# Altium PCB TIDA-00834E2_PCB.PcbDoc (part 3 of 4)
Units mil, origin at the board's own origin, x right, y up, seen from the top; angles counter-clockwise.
Board outline 7480.31 x 4133.86 mil, 4 copper layers (Top Layer, GND, PWR, Bottom Layer), stack 61.912 mil thick; 550 components, 248 nets, 1167 pads, 312 vias.
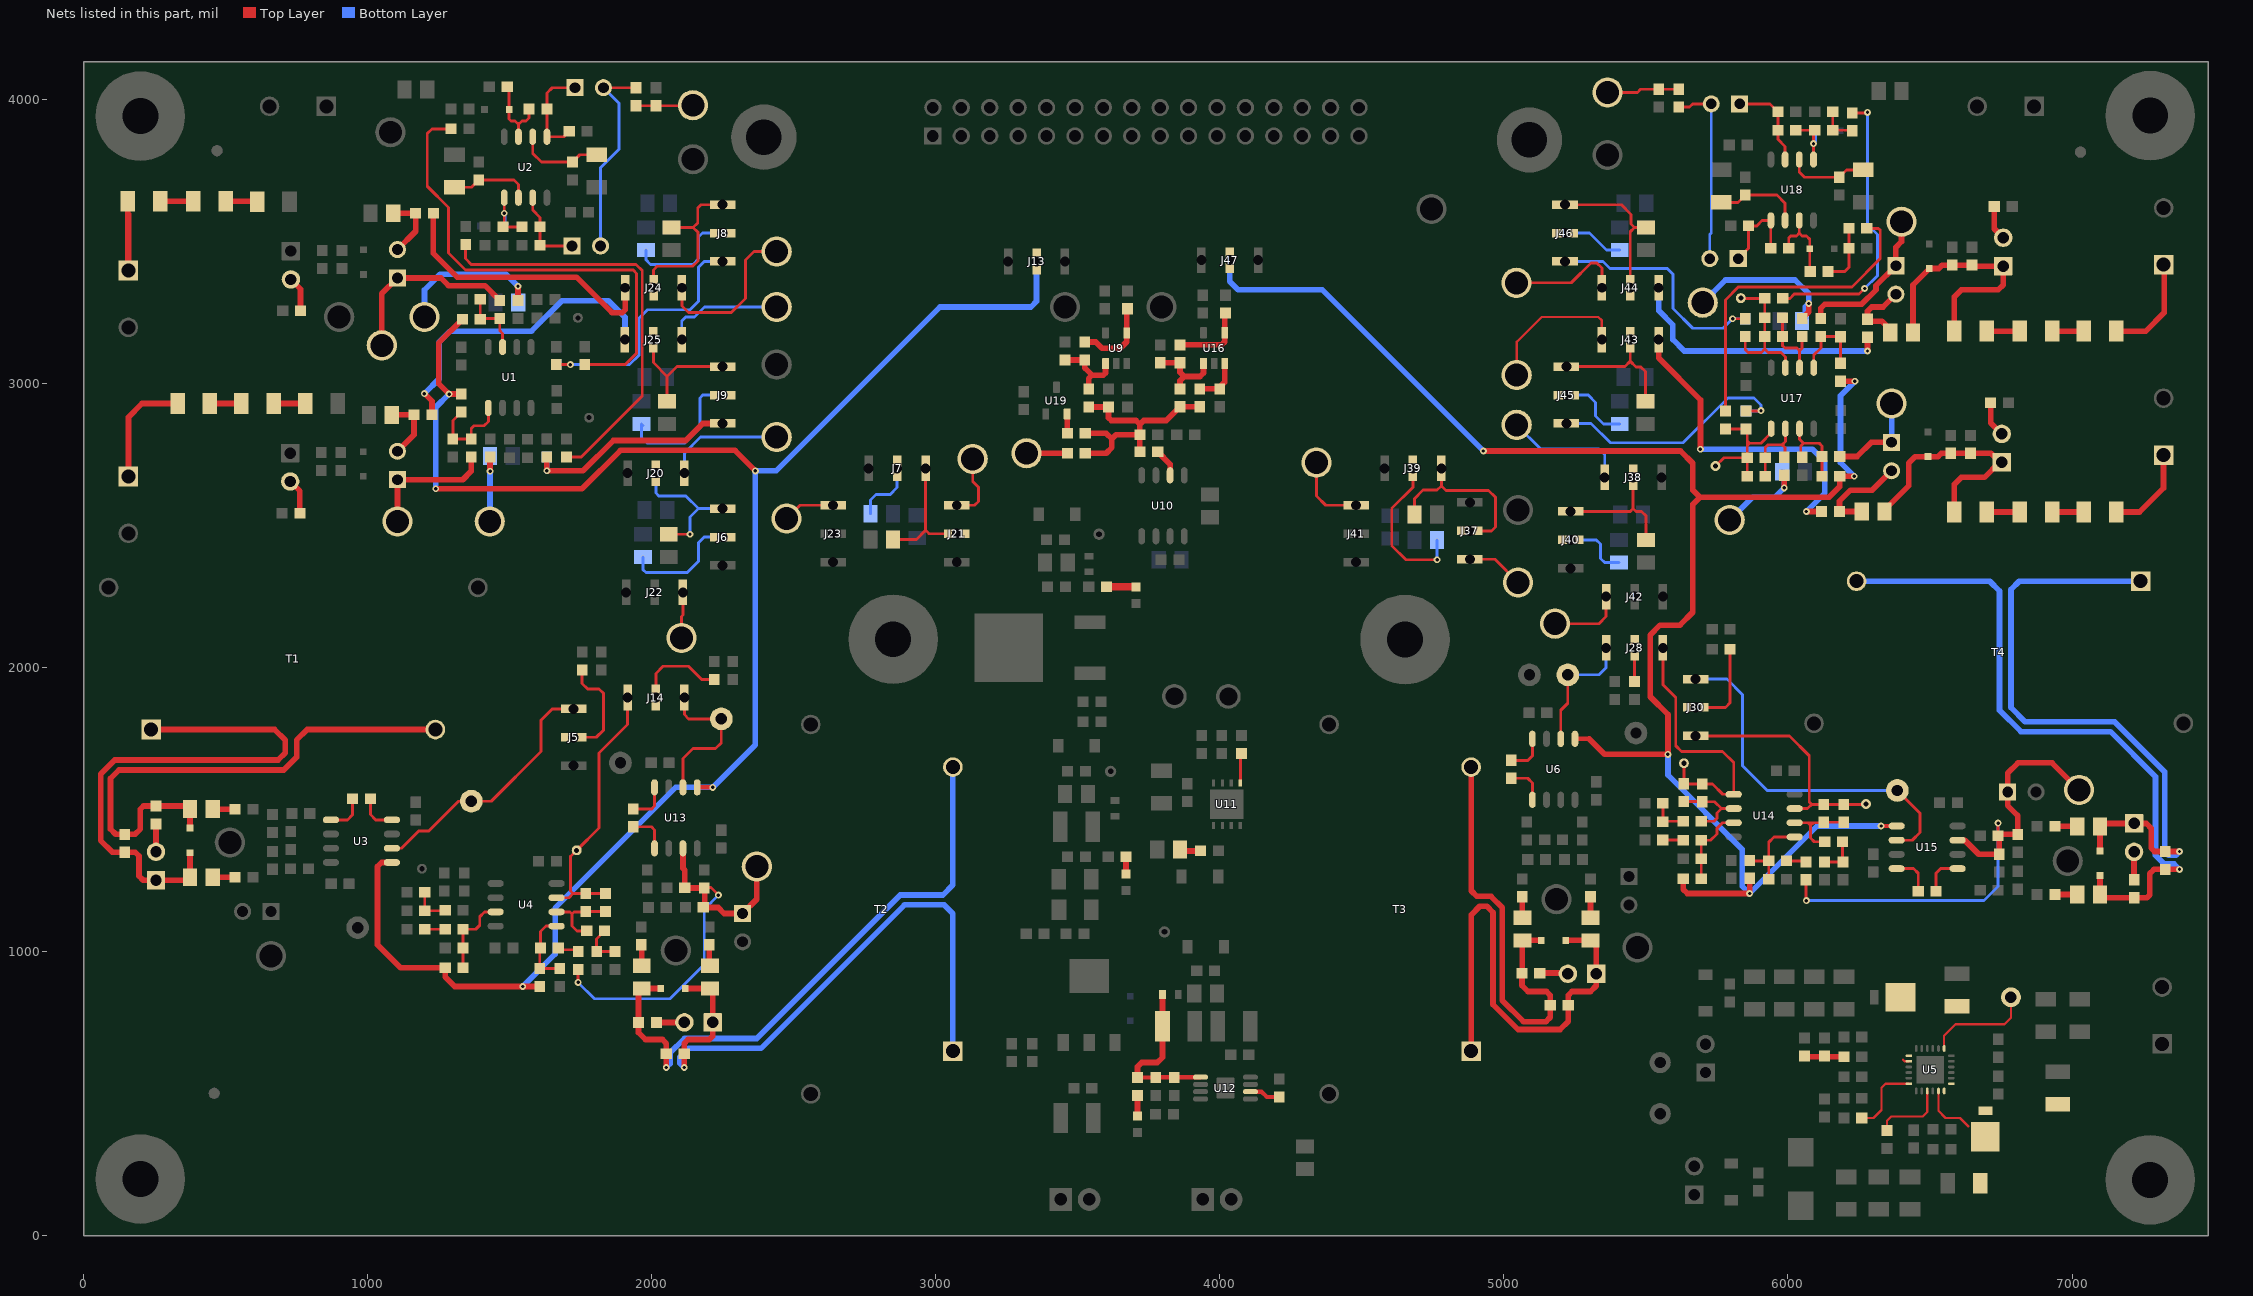
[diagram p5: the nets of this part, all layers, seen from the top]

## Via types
v1: diameter 24, hole 12, Top Layer to Bottom Layer, tented both sides, 295 vias
v2: diameter 19.68, hole 7.87, Top Layer to Bottom Layer, tented both sides, 15 vias
v3: diameter 40, hole 20, Top Layer to Bottom Layer, 2 vias

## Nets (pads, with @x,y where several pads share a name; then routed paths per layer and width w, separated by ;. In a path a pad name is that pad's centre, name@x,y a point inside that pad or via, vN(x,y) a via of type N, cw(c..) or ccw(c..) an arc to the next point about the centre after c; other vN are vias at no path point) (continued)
NetC70_2: C70.2 C72.2 FB3.1 R84.2 R85.2 U12.1 | length 584.2
  Top Layer w15: R84.2@3710.31,557.25 R85.2@3774.04,557.25 3775.44,558.65 U12.1@3932.4,558.65
  Top Layer w20: R84.2@3710.31,557.25 3710.31,595.31 3725,610 3780,610 3798.22,628.22 C72.2@3798.22,737.75 FB3.1@3798.22,850.13
NetC73_1: C73.1 R83.1 | length 74.3
  Top Layer w20: C73.1@3860,1360 3865,1355 R83.1@3932.2,1355
NetC74_2: C74.2 U12.6 | length 109.2
  Top Layer w15: U12.6@4107.6,507.47 4146.84,507.47 4165.54,488.77 C74.2@4209.04,488.77
NetC77_1: C77.1 C78.1 J26.1 R90.2 R104.2 TP25.1 U13.3 | length 1497.1
  Top Layer w10: v1(1741.08,892.32) R104.2@1741.08,937.73 ; R90.2@2185,1224.4 2186.5,1225.9 2208.5,1225.9 v1(2235,1199.4)
  Top Layer w20: U13.3@2110,1364.17 2110,1293.83 2116.5,1287.34 C78.1@2116.5,1225.9 2117.99,1224.4 R90.2@2185,1224.4 2186.5,1222.91 2186.5,1155.9 2234.1,1155.9 2255,1135 J26.1@2320,1135 2370,1185 TP25.1@2370,1300
  Bottom Layer w10: v1(1741.08,892.32) 1798.99,834.4 2064.4,834.4 2185,955 2185,1149.4 v1(2235,1199.4)
NetC82_1: C82.1 R97.2 R98.1 U4.6 | length 280.2
  Top Layer w10: U4.6@1665.24,1140.34 1712.81,1140.34 1719.76,1133.4 ; R98.1@1771.12,1073.4 1736.76,1073.4 1719.76,1090.4 1719.76,1133.4 ; R97.2@1837.61,1141.9 C82.1@1767.61,1141.9 1766.11,1140.4 1726.76,1140.4 1719.76,1133.4
NetC82_2: C82.2 J14.3 R97.1 TP30.1 U4.7 | length 955
  Top Layer w10: U4.7@1665.24,1190.34 1708.7,1190.34 1723.25,1204.89 ; R97.1@1837.61,1204.89 C82.2@1767.61,1204.89 1723.25,1204.89 ; J14.3@1915,1895 1915,1800 1815,1700 1815,1436.24 TP30.1@1736.08,1357.32 1714.76,1336 1714.76,1213.39 1723.25,1204.89
NetC88_1: C88.1 R115.2 R117.1 U14.2 | length 285.9
  Top Layer w10: R115.2@5633.7,1528.5 5697.64,1528.5 C88.1@5698.17,1527.97 5742.03,1527.97 5765.71,1504.29 ; R117.1@5694.66,1459.46 5739.46,1459.46 5750,1470 5750,1488.58 5765.71,1504.29 ; U14.2@5809.09,1504.29 5765.71,1504.29
NetC88_2: C88.2 J28.3 R115.1 TP28.1 U14.1 | length 966.8
  Top Layer w10: J28.3@5560,2070 5560,1940 5605,1895 5605,1725 5625,1705 5770,1705 5809.09,1665.91 U14.1@5809.09,1554.29 5770.71,1554.29 5734.04,1590.96 C88.2@5698.17,1590.96 5634.23,1590.96 R115.1@5633.7,1591.5 TP28.1@5633.7,1663.7
NetC94_1: C94.1 C95.1 J29.1 R123.2 R129.2 TP38.1 U15.3 | length 1876.6
  Top Layer w10: R129.2@6063.7,1253.5 6063.7,1181.3 v1(6065,1180) ; R123.2@6740,1407.8 v1(6740,1452.8)
  Top Layer w20: U15.3@6597.28,1392.8 6622.33,1392.8 6671.81,1343.31 C95.1@6743.51,1343.31 6743.51,1404.29 R123.2@6740,1407.8 6745.52,1413.31 C94.1@6808.5,1413.31 6808.5,1480 6773.5,1515 J29.1@6773.5,1562.8 6773.5,1628.5 6810,1665 6930,1665 TP38.1@7025,1570
  Bottom Layer w10: v1(6065,1180) 6690,1180 6740,1230 v1(6740,1452.8)
NetC99_1: C99.1 R131.2 R133.1 U14.6 | length 299.1
  Top Layer w10: U14.6@6023.65,1454.29 6089.29,1454.29 ; 6070.71,1454.29 6080,1445 ; R133.1@6129.53,1387.34 6092.66,1387.34 6080,1400 6080,1445 ; R131.2@6196.02,1455.84 C99.1@6126.02,1455.84 6124.47,1454.29 6089.29,1454.29 ; 6080,1445 6089.29,1454.29
NetC99_2: C99.2 J30.3 R131.1 TP41.1 U14.7 | length 861.7
  Top Layer w10: J30.3@5675,1760 6005,1760 6075,1690 6075,1527.67 6083.83,1518.83 ; U14.7@6023.65,1504.29 6069.29,1504.29 6083.83,1518.83 ; TP41.1@6275,1520 6273.83,1518.83 R131.1@6196.02,1518.83 C99.2@6126.02,1518.83 6083.83,1518.83
NetC101_1: C101.1 R138.2 R143.1 U17.2 | length 275.5
  Top Layer w10: R138.2@5919.86,2674.33 C101.1@5919.86,2739.33 5919.86,2774.86 5930,2785 5980,2785 ; R143.1@5986.71,2740.82 5990,2744.11 5990,2775 5980,2785 ; U17.2@5990.96,2841.42 5990.96,2795.96 5980,2785
NetC101_2: C101.2 R138.1 R145.1 R200.2 TP44.1 U17.1 | length 487.2
  Top Layer w10: TP44.1@5745,2710 5774.33,2739.33 C101.2@5856.87,2739.33 ; R200.2@5780,2840.55 R145.1@5852.26,2840.55 ; R138.1@5856.87,2674.33 C101.2@5856.87,2739.33 ; 5856.87,2798.13 5865,2790 ; R145.1@5856.87,2835.94 5856.87,2781.87 ; U17.1@5940.96,2841.42 5940.96,2825.96 5905,2790 5865,2790 ; C101.2@5856.87,2739.33 5856.87,2781.87 ; 5856.87,2781.87 5865,2790
NetC102_1: C102.1 R140.2 R146.1 U17.6 | length 278.9
  Top Layer w10: R140.2@5981.33,3232.04 C102.1@5981.33,3165.74 5981.33,3133.67 5990,3125 6031.91,3125 6040.96,3115.96 ; U17.6@6040.96,3055.98 6040.96,3115.96 ; R146.1@6049.84,3165.86 6049.84,3124.84 6040.96,3115.96
NetC102_2: C102.2 R140.1 R147.1 R201.2 TP45.1 U17.7 | length 508.4
  Top Layer w10: TP45.1@5834,3301 5835,3300 R201.2@5918.5,3300 5918.34,3299.84 R140.1@5918.34,3232.04 C102.2@5918.34,3165.74 5918.34,3121.66 ; R147.1@5849.84,3165.55 5849.84,3120.16 5860,3110 5906.68,3110 5918.34,3121.66 ; U17.7@5990.96,3055.98 5990.96,3094.04 5975,3110 5930,3110 5918.34,3121.66
NetC107_2: C107.2 D17.1 JP8.1 L17.1 R148.1 R157.2 | length 830.3
  Top Layer w20: L17.1@6340,2550 6340,2555 6425,2640 6425,2720 6448.19,2743.19 D17.1@6492.83,2743.19 6528.19,2743.19 6540,2755 C107.2@6572.83,2755 R157.2@6630,2755 ; R148.1@6585.83,2547.83 6585.83,2645.83 6610,2670 6691.85,2670 6745,2723.15 6745,2725 6715,2755 R157.2@6642.83,2755
NetC108_2: C108.2 D18.1 JP9.1 L18.1 R153.1 R159.2 | length 896.8
  Top Layer w20: L18.1@6440,3180 6440,3347.48 D18.1@6497.83,3405.31 6531.38,3405.31 6543.19,3417.13 C108.2@6577.83,3417.13 R159.2@6647.83,3417.13 6651.34,3413.62 JP9.1@6757.83,3413.62 6757.83,3347.83 6740,3330 6610,3330 6585.83,3305.83 R153.1@6585.83,3185 R153.1@6582.2,3181.38
NetC109_2: C109.2 R163.2 R164.1 | length 216.2
  Top Layer w10: R164.1@6141.5,3395 6200,3395 6214.63,3409.63 C109.2@6214.63,3476.84 R163.2@6214.63,3546.68
NetC111_2: C111.2 R169.2 R170.1 | length 134.2
  Top Layer w10: C111.2@6157.62,3956.84 R170.1@6157.62,3891.84 6224.47,3891.84 R169.2@6226.12,3890.19
NetC117_2: C117.2 R192.1 U16.3 | length 166.6
  Top Layer w20: R192.1@3930,2981.5 C117.2@4000,2981.5 4000,2988 4017.4,3005.4 U16.3@4017.4,3070.87
NetC120_2: C120.2 R196.2 TP31.1 | length 200.6
  Top Layer w10: R196.2@1945,3978.5 C120.2@2015,3978.5 2143.5,3978.5 TP31.1@2145,3980
NetC121_2: C121.2 R197.2 TP46.1 | length 254.8
  Top Layer w10: TP46.1@5365,4025 5470,4025 5481.5,4036.5 C121.2@5545,4036.5 R197.2@5615,4036.5
NetD3_1: D3.1 JP3.1 L1.1 R37.2 T1.1 | length 1951.6
  Top Layer w20: T1.1@238.19,1782.32 672.68,1782.32 710,1745 710,1700 685,1675 110,1675 60,1625 60,1391.85 101.18,1350.67 181.5,1350.67 195,1337.17 195,1266.85 210,1251.85 JP3.1@255,1251.85 364.68,1251.85 L1.1@375,1262.17 D3.1@375,1348.86
NetD3_2: D3.2 L2.1 R37.1 R39.1 T1.2 | length 1869
  Top Layer w20: D3.2@375,1435.47 L2.1@375,1502.17 363.83,1513.35 R39.1@255,1513.35 211.18,1513.35 200,1502.17 200,1432.17 181.5,1413.66 113.19,1413.66 95,1431.85 95,1610 125,1640 705,1640 750,1685 750,1745 787.32,1782.32 T1.2@1238.19,1782.32
NetD4_1: D4.1 R58.1 U5.23 | length 198.3
  Top Layer w8: U5.23@6530,510 6530,440 6555,415 6605.5,415 6635.5,385
NetD4_2: D4.2 L3.2 U5.1 U5.24
NetD7_1: D7.1 L4.1 U5.13 U5.14 | length 23
  Top Layer w8: 6405,620 6410.67,614.33 U5.14@6425.67,614.33
NetD9_1: D9.1 JP6.1 L7.1 R108.2 T3.1 | length 1674.6
  Top Layer w20: T3.1@4885,650 4885,1130 4915,1160 4940,1160 4962,1138 4962,814.33 5050.2,726.13 5198.13,726.13 5226.5,754.5 R108.2@5226.5,811.85 5226.5,846.5 5240,860 5305,860 5325.32,880.32 JP6.1@5325.32,922.4 5325.32,1019.68 L7.1@5305,1040 D9.1@5218.3,1040
NetD9_2: D9.2 L8.1 R108.1 R110.1 T3.2 | length 1519.7
  Top Layer w20: T3.2@4885,1650 4885,1215 4905,1195 4955,1195 4994,1156 4994,829 5069,754 5148,754 5163.5,769.5 R108.1@5163.5,811.85 5163.5,846.5 5150,860 5085,860 5063.5,881.5 R110.1@5063.5,925 5065,926.49 L8.1@5065,1040 D9.2@5131.69,1040
NetD10_1: D10.1 R71.1 | length 106.5
  Top Layer w20: D10.1@3704.53,2285 D10.1@3705,2284.53 D10.1@3706.97,2286.5
  Top Layer w25: R71.1@3601.5,2285 D10.1@3704.53,2285
NetD12_1: D12.1 R74.1 | length 60.7
  Top Layer w20: R74.1@3670.02,1335 3670.02,1275.04 D12.1@3670.53,1274.53
NetD14_2: D14.2 R84.1 | length 72.2
  Top Layer w20: D14.2@3710.24,422.09 3710.31,422.16 R84.1@3710.31,494.26
NetD15_1: D15.1 JP4.1 L5.1 R91.2 T2.1 | length 2162.4
  Top Layer w20: v1(2114.43,592.72) R91.2@2114.43,640.9 2114.43,677.4 2127.94,690.9 2202.94,690.9 2215,702.97 JP4.1@2215,751.45 L5.1@2215,860.9 ; D15.1@2118.31,870.9 L5.1@2205,870.9
  Bottom Layer w20: v1(2114.43,592.72) 2100,607.15 2100,629.4 2130.6,660 2385,660 2890,1165 3030,1165 3060,1135 T2.1@3060,650
NetD15_2: D15.2 L6.1 R91.1 R93.1 T2.2 | length 2137.3
  Top Layer w20: D15.2@2031.69,870.9 L6.1@1965,870.9 1953.51,859.4 R93.1@1953.51,750.9 1953.51,715.33 1977.94,690.9 2037.94,690.9 2051.44,677.4 R91.1@2051.44,640.9 v1(2051.44,592.72)
  Bottom Layer w20: v1(2051.44,592.72) 2065,606.28 2065,644.4 2115.6,695 2370,695 2875,1200 3025,1200 3060,1235 T2.2@3060,1650
NetD16_1: D16.1 JP7.1 L9.1 R124.2 T4.1 | length 2314.9
  Top Layer w20: D16.1@7098.51,1354.8 L9.1@7098.5,1441.5 7108.82,1451.81 JP7.1@7218.51,1451.81 7261.69,1451.81 7278.5,1435 7278.5,1365 7290.51,1352.99 R124.2@7328.5,1352.99 v1(7378.5,1352.99)
  Bottom Layer w20: T4.1@7241.81,2304.41 6814.41,2304.41 6785,2275 6785,1860 6835,1810 7150,1810 7326,1634 7326,1354.5 7340.5,1340 7365.5,1340 v1(7378.5,1352.99)
NetD16_2: D16.2 L10.1 R124.1 R126.1 T4.2 | length 2401.4
  Top Layer w20: D16.2@7098.51,1268.18 L10.1@7098.5,1201.49 7109.68,1190.32 R126.1@7218.51,1190.32 7263.82,1190.32 7273.5,1200 7273.5,1275 7288.5,1290 R124.1@7328.5,1290 v1(7378.5,1290)
  Bottom Layer w20: T4.2@6241.81,2304.41 6710.59,2304.41 6745,2270 6745,1850 6820,1775 7135,1775 7294,1616 7294,1339.5 7324.5,1309 7359.5,1309 v1(7378.5,1290)
NetD19_1: D19.1 R23.2 R27.2 U2.3 | length 278.7
  Top Layer w10: R27.2@1491.5,4045 1498.31,4038.19 D19.1@1498.31,3965 1498.31,3931.69 1505,3925 1519.09,3925 1531.12,3912.97 ; U2.3@1531.12,3869.14 1531.12,3912.97 ; R23.2@1568.5,3966.85 1568.5,3935.36 1558.15,3925 1543.15,3925 1531.12,3912.97
NetD20_1: D20.1 R29.2 R33.2 U2.5 | length 217.5
  Top Layer w10: U2.5@1481.12,3654.57 v1(1481.12,3600) 1481.12,3556.47 R33.2@1476.5,3551.85 R29.2@1543.5,3551.85
  Bottom Layer w10: v1(1481.12,3600) 1483.31,3597.81 D20.1@1483.31,3555
NetD21_1: D21.1 R160.2 R164.2 U18.3 | length 284.9
  Top Layer w10: R160.2@6002.78,3476.68 R160.2@6002.62,3476.84 6002.62,3512.62 6010,3520 6030,3520 6040,3530 ; U18.3@6040,3574.56 6040,3530 ; R164.2@6078.5,3395 6076.69,3396.81 D21.1@6076.69,3475 6076.69,3508.31 6065,3520 6050.01,3520 6040,3530
NetD22_1: D22.1 R166.2 R170.2 U18.5 | length 219.4
  Top Layer w10: R166.2@6027.62,3891.84 R170.2@6094.63,3891.84 6090,3887.22 U18.5@6090,3789.13
  Bottom Layer w10: v1(6090,3845) 6096.69,3851.69 D22.1@6096.69,3890
NetJ1_1: J1.1 R2.2 | length 443.6
  Top Layer w20: R2.2@155.83,3642.36 155.83,3399.88 J1.1@157.48,3398.23 157.91,3398.66 157.91,3596.85
NetJ2_1: J2.1 R4.2 | length 406.9
  Top Layer w20: J2.1@161.22,2669.49 J2.1@157.48,2673.23 157.91,2673.66 157.91,2881.85 206.06,2930 R4.2@330.83,2930
NetJ3_1: J3.1 R23.1 R25.1 U2.1 | length 347.1
  Top Layer w10: R25.1@1709.62,3888.51 1690.25,3869.14 U2.1@1631.12,3869.14 1631.12,3966.47 R23.1@1631.5,3966.85 1631.5,4023.35 1650,4041.85 J3.1@1730,4041.85
NetJ3_2: J3.2 J4.2 R196.1 | length 721.7
  Top Layer w10: J3.2@1830,4041.85 1830.35,4041.5 R196.1@1945,4041.5
  Bottom Layer w10: J4.2@1820,3485 1820,3760 1885,3825 1885,3986.85 J3.2@1830,4041.85
NetJ4_1: J4.1 R29.1 R31.1 U2.7 | length 292.5
  Top Layer w10: U2.7@1581.12,3654.57 1581.12,3610.74 1606.5,3585.36 R29.1@1606.5,3551.85 R31.1@1606.5,3486.85 1608.35,3485 J4.1@1720,3485
NetJ5_1: J5.1 TP7.1 U3.6 | length 907.2
  Top Layer w10: U3.6@1085.47,1364.33 1119.33,1364.33 1180,1425 1215,1425 1320,1530 TP7.1@1365,1530 1435,1530 1610,1705 1610,1815 1650,1855 J5.1@1725,1855
NetJ5_2: J5.2 R45.1 | length 381.6
  Top Layer w10: J5.2@1725,1755 1805,1755 1830,1780 1830,1910 1815,1925 1775,1925 1755,1945 R45.1@1755,1991.76
NetJ6_1: J6.1 J20.2 R181.2 | length 505.2
  Top Layer w10: R181.2@2060,2470 v1(2135,2470)
  Bottom Layer w10: J20.2@2015,2685 2015,2615 2025,2605 2120,2605 2165,2560 ; v1(2135,2470) 2135,2530 2165,2560 ; J6.1@2250,2560 2165,2560
NetJ6_2: J6.2 R49.1 | length 419
  Bottom Layer w10: R49.1@1970,2390 1970,2345 1980,2335 2125,2335 2165,2375 2165,2440 2185,2460 J6.2@2250,2460
NetJ7_1: J7.1 J21.2 R182.2 | length 460.2
  Top Layer w10: R182.2@2850,2451.85 2931.85,2451.85 2964,2484 ; J7.1@2964,2701.85 2964,2484 ; J21.2@3074,2471.85 2976.15,2471.85 2964,2484
NetJ7_2: J7.2 R50.1 | length 228.2
  Bottom Layer w10: R50.1@2770,2541.85 2770,2590 2790,2610 2840,2610 2864,2634 J7.2@2864,2701.85
NetJ8_1: J8.1 J24.2 R188.2 | length 601
  Top Layer w10: J24.2@2006.57,3337.64 2006.57,3400.57 2019,3413 2144,3413 2163,3432 2163,3533 2146,3550 ; R188.2@2070,3550 2146,3550 ; J8.1@2250,3630 2174,3630 2162,3618 2162,3566 2146,3550
NetJ8_2: J8.2 R53.1 | length 400.7
  Bottom Layer w10: R53.1@1980,3470 1980,3436 1996,3420 2145,3420 2165,3440 2165,3516 2179,3530 J8.2@2250,3530
NetJ9_1: J9.1 J25.2 R185.2 | length 446.8
  Top Layer w10: J25.2@2006.01,3155 2006.01,3073.99 2054.43,3025.57 ; R185.2@2054.43,2938.05 2054.43,3025.57 ; J9.1@2250,3060 2088.87,3060 2054.43,3025.57
NetJ9_2: J9.2 R54.1 | length 481.4
  Bottom Layer w10: R54.1@1970,2852.49 R54.1@1964.43,2858.05 1964.43,2810.57 1985,2790 2115,2790 2170,2845 2170,2950 2180,2960 J9.2@2250,2960
NetJ14_1: J14.1 TP27.1 U13.6 | length 540.3
  Top Layer w10: U13.6@2110,1578.73 2110,1680 2145,1715 2225,1715 2245,1735 TP27.1@2245,1820 2130,1820 2115,1835 J14.1@2115,1895
NetJ14_2: J14.2 R99.1 | length 319.6
  Top Layer w10: J14.2@2015,1895 2015,1980 2040,2005 2130,2005 2176.5,1958.5 R99.1@2220,1958.5
NetJ17_1: J17.1 R12.2 TP57.1 | length 652.4
  Top Layer w20: TP57.1@1050,3135 1050,3316.85 J17.1@1105,3371.85 1258.15,3371.85 1285,3345 1412.72,3345 R12.2@1465,3292.72
NetJ17_2: J17.2 L13.2 R198.2 | length 237.2
  Top Layer w20: L13.2@1090,3600 1167.5,3600 1169.5,3602 1169.5,3536.35 J17.2@1105,3471.85
NetJ18_1: J18.1 R13.2 TP58.1 | length 469
  Top Layer w20: TP58.1@1105,2515 J18.1@1105,2661.85 1334.85,2661.85 1365,2692 R13.2@1365,2741.7
NetJ18_2: J18.2 L14.2 R199.2 | length 230.9
  Top Layer w20: L14.2@1085,2890 R199.2@1163.5,2890 1163.5,2820.35 J18.2@1105,2761.85
NetJ20_1: J20.1 TP11.1 | length 418.5
  Bottom Layer w10: J20.1@2115,2685 2115,2755 2171.85,2811.85 TP11.1@2440,2811.85
NetJ21_1: J21.1 TP12.1 | length 239.7
  Top Layer w10: J21.1@3074,2571.85 3136.85,2571.85 3150,2585 3150,2635 3130,2655 TP12.1@3130,2735
NetJ22_1: J22.1 TP18.1 | length 162.1
  Top Layer w10: TP18.1@2105,2105 2105,2180 2110,2185 J22.1@2110,2265
NetJ23_1: J23.1 TP35.1 | length 183.4
  Top Layer w10: TP35.1@2475,2525 2521.85,2571.85 J23.1@2639,2571.85
NetJ24_1: J24.1 TP13.1 | length 575.5
  Top Layer w10: J24.1@2106.57,3337.64 2106.57,3273.43 2130,3250 2280,3250 2330,3300 2330,3435 2360,3465 TP13.1@2440,3465
NetJ25_1: J25.1 TP14.1 | length 420.3
  Bottom Layer w10: J25.1@2106.01,3155 2106.01,3221.01 2120,3235 2151,3235 2186,3270 TP14.1@2440,3270
NetJ28_1: J28.1 TP8.1 U6.6 | length 450.9
  Top Layer w10: U6.6@5200.31,1749.69 5200.31,1850.31 5225,1875 TP8.1@5225,1975
  Bottom Layer w10: TP8.1@5225,1975 5335,1975 5360,2000 J28.1@5360,2070
NetJ28_2: J28.2 R118.1 | length 118.5
  Top Layer w10: R118.1@5460,1951.5 J28.2@5460,2070
NetJ30_1: J30.1 TP39.1 U15.6 | length 1293.4
  Top Layer w10: U15.6@6382.72,1392.8 6437.8,1392.8 6465,1420 6465,1487.8 TP39.1@6385,1567.8
  Bottom Layer w10: J30.1@5675,1960 5785,1960 5840,1905 5840,1655 5927.2,1567.8 TP39.1@6385,1567.8
NetJ30_2: J30.2 R134.1 | length 316.8
  Top Layer w10: J30.2@5675,1860 5780,1860 5796.5,1876.5 R134.1@5796.5,2065
NetJ31_1: J31.1 R139.2 | length 318.7
  Top Layer w20: R139.2@7155,2547.83 7237.83,2547.83 7322.09,2632.09 7322.09,2748.19 J31.1@7322.52,2748.62
NetJ32_1: J32.1 R149.2 TP63.1 | length 339.8
  Top Layer w20: R149.2@6182.45,2743.7 6243.7,2743.7 6293.35,2793.35 J32.1@6365,2793.35
  Bottom Layer w20: J32.1@6365,2793.35 TP63.1@6365,2930
NetJ32_2: J32.2 L17.2 R202.2 | length 342.8
  Top Layer w20: L17.2@6260,2550 R202.2@6181.5,2550 6181.5,2586.5 6220,2625 6296.65,2625 J32.2@6365,2693.35
NetJ33_1: J33.1 R150.2 TP64.1 | length 535
  Top Layer w20: R150.2@6115.96,3228.85 6115.96,3265.96 6130,3280 6260,3280 6310,3330 6310,3345 J33.1@6380,3415 6380,3480 6400,3500 TP64.1@6400,3570
NetJ33_2: J33.2 L18.2 R203.2 | length 258.5
  Top Layer w20: L18.2@6360,3180 6360,3190 6330,3220 6286.5,3220 R203.2@6280,3226.5 6280,3255 6295,3270 6335,3270 J33.2@6380,3315
NetJ34_1: J34.1 R141.2 | length 366.3
  Top Layer w20: R141.2@7155,3185 7259.92,3185 7324.92,3250 7324.92,3416.54 J34.1@7322.83,3418.62
NetJ35_1: J35.1 R160.1 R162.1 U18.1 | length 313.6
  Top Layer w10: J35.1@5825,3440 5861.5,3476.5 R162.1@5861.5,3555.19 5890.19,3555.19 5909.19,3574.19 5939.63,3574.19 R160.1@5939.63,3476.84
NetJ35_2: J35.2 J36.2 R197.1 | length 666.8
  Top Layer w10: R197.1@5615,3973.5 5653.5,3973.5 5665,3985 J36.2@5730,3985
  Bottom Layer w10: J35.2@5725,3440 5725,3525 5730,3530 J36.2@5730,3985
NetJ36_1: J36.1 R166.1 R168.1 U18.7 | length 324.4
  Top Layer w10: J36.1@5830,3985 5936.31,3985 R168.1@5964.63,3956.68 R166.1@5964.63,3891.84 5964.63,3860.37 5990,3835 U18.7@5990,3789.13
NetJ37_1: J37.1 TP47.1 | length 203.9
  Top Layer w10: J37.1@4880,2381.85 4968.15,2381.85 TP47.1@5050,2300
NetJ37_2: J37.2 J39.1 R183.2 | length 637.5
  Top Layer w10: R183.2@4685,2540 4685,2595 4715,2625 4765,2625 4780,2640 ; J39.1@4780,2701.85 4780,2640 ; J37.2@4880,2481.85 4956.85,2481.85 4970,2495 4970,2600 4946.16,2623.84 4796.16,2623.84 4780,2640
NetJ38_1: J38.1 TP48.1 | length 433.5
  Bottom Layer w10: TP48.1@5045,2855 5130,2770 5335,2770 5355,2750 J38.1@5355,2670.01
NetJ38_2: J38.2 J40.1 R184.2 | length 474.5
  Top Layer w10: J40.1@5235,2550.01 5445.01,2550.01 5455,2560 ; J38.2@5455,2670.01 5455,2560 ; R184.2@5500,2450 5500,2535 5485,2550 5465,2550 5455,2560
NetJ39_2: J39.2 R173.1 | length 553.6
  Top Layer w10: J39.2@4680,2701.85 4680,2635 4605,2560 4605,2430 4655,2380 v1(4765,2380)
  Bottom Layer w10: v1(4765,2380) R173.1@4765,2450
NetJ40_2: J40.2 R174.1 | length 232.4
  Bottom Layer w10: J40.2@5235,2450.01 5324.99,2450.01 5340,2435 5340,2385 5354.99,2370.01 R174.1@5405,2370.01
NetJ41_1: J41.1 TP49.1 | length 270.6
  Top Layer w10: TP49.1@4340,2721.85 4340,2605 4373.15,2571.85 J41.1@4480,2571.85
NetJ42_1: J42.1 TP50.1 | length 260.4
  Top Layer w10: TP50.1@5180,2155 5335,2155 5360,2180 J42.1@5360,2250
NetJ43_1: J43.1 TP52.1 | length 525.8
  Top Layer w8: TP52.1@5045,3030 5045,3147 5133,3235 5332,3235 5345,3222 J43.1@5345,3154.99
NetJ43_2: J43.2 J45.1 R186.2 | length 481.7
  Top Layer w10: J45.1@5220,3060 5426,3060 5445,3079 ; J43.2@5445,3154.99 5445,3079 ; R186.2@5498,2938.05 5498,3043 5482,3059 5465,3059 5445,3079
NetJ44_1: J44.1 TP51.1 | length 406.8
  Top Layer w10: TP51.1@5044,3355 5237,3355 5307,3425 5327,3425 5345,3407 J44.1@5345,3337.62
NetJ44_2: J44.2 J46.1 R187.2 | length 557
  Top Layer w10: J46.1@5215,3630 5414,3630 5448,3596 5448,3562.38 5460.38,3550 ; J44.2@5445,3337.62 5445,3534.62 5460.38,3550 ; R187.2@5500.38,3550 5460.38,3550
NetJ45_2: J45.2 R177.1 | length 258.3
  Bottom Layer w10: J45.2@5220,2960 5297,2960 5323,2934 5323,2886 5350.95,2858.05 R177.1@5408,2858.05
NetJ46_2: J46.2 R178.1 | length 217.9
  Bottom Layer w10: J46.2@5215,3530 5301,3530 5361,3470 R178.1@5408,3470
NetJP1_2: JP1.2 R19.2 | length 124.1
  Top Layer w20: JP1.2@730,3366.85 764.02,3332.83 R19.2@764.02,3256.85
NetJP2_2: JP2.2 R21.2 | length 125.5
  Top Layer w20: JP2.2@727.48,2655.59 761.5,2621.57 R21.2@761.5,2544.21
NetJP3_2: JP3.2 R39.2 | length 98.5
  Top Layer w20: JP3.2@255,1351.85 R39.2@255,1450.35
NetJP4_2: JP4.2 R93.2 | length 98.7
  Top Layer w20: R93.2@2016.5,750.9 2114.45,750.9 JP4.2@2115,751.45
NetJP6_2: JP6.2 R110.2 | length 99.9
  Top Layer w20: R110.2@5126.5,925 5222.72,925 JP6.2@5225.32,922.4
NetJP7_2: JP7.2 R126.2 | length 98.5
  Top Layer w20: R126.2@7218.51,1253.31 JP7.2@7218.51,1351.81
NetJP8_2: JP8.2 R156.2 | length 126.3
  Top Layer w20: R156.2@6713.5,2933.15 6713.5,2862.48 JP8.2@6752.83,2823.15
NetJP9_2: JP9.2 R158.2 | length 123
  Top Layer w20: R158.2@6726.34,3623.62 6726.34,3545.12 JP9.2@6757.83,3513.62
NetL1_2: L1.2 R35.1 | length 78.5
  Top Layer w20: L1.2@455,1262.17 R35.1@533.5,1262.17
NetL2_2: L2.2 R41.1 | length 78.5
  Top Layer w20: L2.2@455,1502.17 R41.1@533.5,1502.17
NetL5_2: L5.2 R89.1 | length 74.4
  Top Layer w20: R89.1@2202.94,1024.4 2202.94,952.97 L5.2@2205,950.9
NetL6_2: L6.2 R95.1 | length 71.4
  Top Layer w20: L6.2@1965,950.9 R95.1@1965,1022.34
NetL7_2: L7.2 R106.1 | length 73.5
  Top Layer w20: L7.2@5305,1120 R106.1@5305,1193.5
NetL8_2: L8.2 R112.1 | length 73.5
  Top Layer w20: L8.2@5065,1120 R112.1@5065,1193.5
NetL9_2: L9.2 R122.1 | length 78.5
  Top Layer w20: R122.1@6940,1441.5 L9.2@7018.5,1441.5
NetL10_2: L10.2 R128.1 | length 78.5
  Top Layer w20: R128.1@6940,1201.5 L10.2@7018.5,1201.49
NetL11_2: L11.2 R6.2 TP1.1 | length 572.6
  Top Layer w20: R6.2@1529.25,3292.72 v1(1529.25,3342.74)
  Bottom Layer w20: TP1.1@1200,3235 1200,3330 1255,3385 1486.99,3385 v1(1529.25,3342.74) 1530,3341.99 L11.2@1530,3285
NetL12_2: L12.2 R9.2 TP2.1 | length 280.5
  Top Layer w20: v1(1431.12,2691.68) R9.2@1431.12,2741.7
  Bottom Layer w20: TP2.1@1430,2515 1431.12,2516.12 v1(1431.12,2691.68) ; v1(1431.12,2691.68) L12.2@1431.14,2745
NetL15_2: L15.2 R143.2 TP42.1 | length 343.4
  Top Layer w20: v1(5986.71,2632.83) R143.2@5986.71,2677.83
  Bottom Layer w20: TP42.1@5795,2520 5875,2600 5953.88,2600 v1(5986.71,2632.83) 5986.71,2683.29 L15.2@5980,2690
NetL16_2: L16.2 R146.2 TP43.1 | length 595.3
  Top Layer w20: R146.2@6049.84,3228.85 6073,3252.02 v1(6073,3282)
  Bottom Layer w20: TP43.1@5700,3285 5780,3365 6025,3365 6073,3317 v1(6073,3282) 6061.87,3270.87 6061.87,3231.87 L16.2@6050,3220
NetR2_1: R2.1 R5.2 | length 115.8
  Top Layer w20: R2.1@270,3642.36 R5.2@385.83,3642.36
NetR4_1: R4.1 R7.2 | length 110.8
  Top Layer w20: R4.1@445,2930 R7.2@555.83,2930
NetR5_1: R5.1 R11.2 | length 108.5
  Top Layer w20: R5.1@500,3642.36 R11.2@608.46,3642.36
NetR7_1: R7.1 R16.2 | length 110.8
  Top Layer w20: R7.1@670,2930 R16.2@780.83,2930
NetR12_1: R12.1 R14.2 R15.2 U1.3 | length 244.4
  Top Layer w10: R15.2@1396.5,3296.85 R14.2@1396.5,3226.85 1399.37,3229.73 R12.1@1465,3229.73 1465,3186.85 1475,3176.85 U1.3@1475,3129.14
NetR13_1: R13.1 R17.2 R18.2 U1.5 | length 328.3
  Top Layer w10: R17.2@1330,2900.36 1300,2870.36 R18.2@1300,2804.69 R13.1@1365,2804.69 1365,2841.85 1375,2851.85 1410,2851.85 1425,2866.85 U1.5@1425,2914.57
NetR24_1: R24.1 R28.2 U2.2 | length 306.7
  Top Layer w10: U2.2@1581.12,3869.14 1581.12,3810.74 1611.85,3780 R24.1@1721.12,3780 1746.71,3805.6 R28.2@1806.12,3805.6
NetR30_1: R30.1 R34.2 U2.6 | length 288.5
  Top Layer w10: R34.2@1306.12,3691.42 1365.53,3691.42 R30.1@1391.12,3717.01 1514.84,3717.01 1531.12,3700.74 U2.6@1531.12,3654.57
NetR38_1: R38.1 U3.1 | length 140.3
  Top Layer w10: U3.1@870.91,1464.33 928.87,1464.33 946.69,1482.15 R38.1@946.69,1539.33
NetR38_2: R38.2 U3.8 | length 139.8
  Top Layer w10: R38.2@1009.69,1539.33 1009.69,1483.15 1028.51,1464.33 U3.8@1085.47,1464.33
NetR42_2: R42.2 R44.2 R62.1 | length 137.6
  Top Layer w10: R42.2@1201.17,1209.4 R62.1@1201.17,1144.4 1272.14,1144.4 R44.2@1273.26,1145.52
NetR46_1: R46.1 R47.2 R48.2 U4.3 | length 293.2
  Top Layer w10: R47.2@1336.25,943.4 R48.2@1336.25,1013.4 1336.25,1079.32 1380.68,1079.32 1394.76,1093.4 1394.76,1123.4 1411.7,1140.34 U4.3@1450.67,1140.34
NetR46_2: R46.2 R57.1 | length 72
  Top Layer w10: R57.1@1201.17,1079.4 R46.2@1273.18,1079.4
NetR63_1: R63.1 U5.18 | length 261.3
  Top Layer w8: R63.1@6260,415 6301,415 6329,443 6329,521 6343.59,535.59 U5.18@6425.67,535.59
NetR64_2: R64.2 R65.1 R67.2 | length 135
  Top Layer w20: R65.1@6062.01,630 R64.2@6197.01,630
NetR69_1: R69.1 U5.21 | length 263.2
  Top Layer w8: R69.1@6348.82,370.67 6348.82,405 6363.82,420 6475,420 6490.63,435.63 U5.21@6490.63,510
NetR72_1: R72.1 R73.1 R77.2 U9.1 | length 271.7
  Top Layer w20: R77.2@3455,3083.5 R73.1@3525,3083.5 3525,3055 3550,3030 ; R72.1@3538.15,2980.75 3538.15,3018.15 3550,3030 ; U9.1@3597.6,3070.55 3597.6,3037.6 3590,3030 3550,3030
NetR72_2: R72.2 R78.2 R81.1 R189.2 R192.2 R193.2 R194.2 R195.2 | length 889.8
  Top Layer w20: R194.2@3526.5,2755 3600,2755 3620,2775 3620,2805 ; R193.2@3526.5,2825 3600,2825 3620,2805 ; R72.2@3538.15,2917.76 R78.2@3608.15,2917.76 3608.15,2880 3618.15,2870 3705,2870 3718.5,2856.5 ; R195.2@3718.5,2760 R81.1@3718.5,2820 ; R189.2@3860,2918.5 3811.5,2870 3732.01,2870 3718.5,2856.5 ; R189.2@3870,2918.5 R192.2@3930,2918.5 ; 3620,2805 3635,2820 R81.1@3718.5,2820 ; R81.1@3718.5,2820 3718.5,2856.5
NetR73_2: R73.2 R206.1 U9.4 | length 283
  Top Layer w20: R73.2@3525,3146.5 3563.5,3146.5 3585.31,3124.69 3649.69,3124.69 3672.4,3147.4 U9.4@3672.4,3178.82 3672.4,3260.91 R206.1@3675,3263.5
NetR82_1: R82.1 U11.5 | length 106
  Top Layer w10: U11.5@4072.24,1594.17 4072.24,1694.45 R82.1@4076.3,1698.5
NetR92_1: R92.1 U13.1 | length 144.3
  Top Layer w10: R92.1@1935,1439.95 1998.88,1439.95 2010,1428.83 U13.1@2010,1364.17
NetR92_2: R92.2 U13.8 | length 144.9
  Top Layer w10: R92.2@1935,1502.95 1999.98,1502.95 2010,1512.97 U13.8@2010,1578.73
NetR96_1: R96.1 R98.2 R105.1 | length 149.3
  Top Layer w10: R98.2@1834.11,1073.4 1806.08,1045.37 R96.1@1806.08,1000.66 R105.1@1871.08,1000.66
NetR100_1: R100.1 R101.2 R102.2 U4.5 | length 266.2
  Top Layer w10: U4.5@1665.24,1090.34 1627.53,1090.34 1608.26,1071.07 R100.1@1608.26,1013.4 1606.08,1011.21 R101.2@1606.08,940.72 R102.2@1676.08,940.72
NetR100_2: R100.2 R104.1 | length 75.1
  Top Layer w10: R100.2@1671.25,1013.4 1677.34,1007.32 1734.48,1007.32 R104.1@1741.08,1000.72
NetR109_1: R109.1 U6.1 | length 141.3
  Top Layer w10: R109.1@5025.32,1610.91 5084.09,1610.91 5100.31,1594.69 U6.1@5100.31,1535.12
NetR109_2: R109.2 U6.8 | length 141.2
  Top Layer w10: R109.2@5025.32,1673.9 5083.9,1673.9 5100.31,1690.31 U6.8@5100.31,1749.69
NetR113_1: R113.1 R119.2 | length 72.2
  Top Layer w10: R113.1@5559.59,1393.34 5631.05,1393.34 R119.2@5631.59,1392.8
NetR114_1: R114.1 R116.2 R117.2 | length 137.6
  Top Layer w10: R114.1@5559.59,1523.34 R116.2@5559.59,1458.34 5560.71,1459.46 R117.2@5631.67,1459.46
NetR119_1: R119.1 R120.2 R121.2 U14.3 | length 287.2
  Top Layer w10: R120.2@5694.66,1257.34 R121.2@5694.66,1327.34 5694.59,1327.42 R119.1@5694.59,1392.8 5727.8,1392.8 5750,1415 5750,1435 5769.29,1454.29 U14.3@5809.09,1454.29
NetR125_1: R125.1 U15.1 | length 146.2
  Top Layer w10: R125.1@6521.5,1212.8 6521.5,1276.5 6537.8,1292.8 U15.1@6597.28,1292.8
NetR125_2: R125.2 U15.8 | length 146.2
  Top Layer w10: U15.8@6382.72,1292.8 6442.2,1292.8 6458.5,1276.5 R125.2@6458.5,1212.8
NetR129_1: R129.1 R135.2 | length 70
  Top Layer w10: R135.2@5995.2,1320 6060.2,1320 R129.1@6063.7,1316.5
NetR130_1: R130.1 R132.1 R133.2 | length 136.3
  Top Layer w10: R132.1@6128.7,1316.5 R130.1@6193.7,1316.5 6192.52,1317.68 R133.2@6192.52,1387.34
NetR135_1: R135.1 R136.2 R137.2 U14.5 | length 297.7
  Top Layer w10: R136.2@5865,1321.5 5866.5,1320 R135.1@5932.2,1320 ; R137.2@5932.2,1255 R135.1@5932.2,1320 ; U14.5@6023.65,1404.29 5950.74,1404.29 5932.2,1385.75 R135.1@5932.2,1320
NetR139_1: R139.1 R142.2 | length 110.8
  Top Layer w20: R142.2@6930,2547.83 R139.1@7040.83,2547.83
NetR141_1: R141.1 R144.2 | length 110.8
  Top Layer w20: R144.2@6930,3185 R141.1@7040.83,3185
NetR142_1: R142.1 R148.2 | length 115.8
  Top Layer w20: R148.2@6700,2547.83 R142.1@6815.83,2547.83
NetR144_1: R144.1 R153.2 | length 115.8
  Top Layer w20: R153.2@6700,3185 R144.1@6815.83,3185
NetR149_1: R149.1 R151.2 R152.2 U17.3 | length 288.2
  Top Layer w10: U17.3@6040.96,2841.42 6040.96,2804.04 6055,2790 ; R152.2@6050.96,2740.82 6045,2746.78 6045,2780 6055,2790 ; R151.2@6119.46,2673.7 R149.1@6119.46,2743.7 6119.46,2780.54 6110,2790 6055,2790
NetR150_1: R150.1 R154.2 R155.2 U17.5 | length 283.3
  Top Layer w10: U17.5@6090.96,3055.98 6090.96,3100.96 6115.96,3125.96 R150.1@6115.96,3165.86 6184.49,3165.86 R155.2@6185,3165.35 R154.2@6185,3071.5
NetR161_1: R161.1 R165.2 U18.2 | length 307.9
  Top Layer w10: R165.2@5765,3638.1 5824.41,3638.1 R161.1@5850,3663.69 5961.31,3663.69 5990,3635 U18.2@5990,3574.56
NetR167_1: R167.1 R171.2 U18.6 | length 287.3
  Top Layer w10: U18.6@6040,3789.13 6040,3745 6058.32,3726.68 R167.1@6180,3726.68 6205.59,3752.27 R171.2@6265,3752.27
NetR189_1: R189.1 R190.1 R191.2 U16.1 | length 280.5
  Top Layer w20: R191.2@3790,3073.5 R190.1@3860,3073.5 3860,3040 3875,3025 ; R189.1@3860,2981.5 3860,3010 3875,3025 ; U16.1@3942.6,3070.87 3942.6,3037.6 3930,3025 3875,3025
NetR190_2: R190.2 R207.1 U16.4 | length 264.1
  Top Layer w20: R190.2@3860,3136.5 4006.5,3136.5 4017.4,3147.4 U16.4@4017.4,3179.13 4017.4,3245.91 R207.1@4020,3248.5
NetR193_1: R193.1 U19.2 | length 68.2
  Top Layer w20: U19.2@3462.4,2892.76 3462.4,2826.1 R193.1@3463.5,2825
NetR194_1: R194.1 TP56.1 | length 143.5
  Top Layer w20: TP56.1@3320,2755 R194.1@3463.5,2755
NetR195_1: R195.1 U10.6 | length 100.7
  Top Layer w20: R195.1@3781.5,2760 3825,2716.5 U10.6@3825,2677.28
NetTP17_1: TP17.1 U5.7 | length 378.6
  Top Layer w8: U5.7@6549.69,659.61 6549.69,704.68 6590,745 6762,745 6785,768 TP17.1@6785,840
PD1_IN_+: J24.3 R198.1 | length 984.9
  Top Layer w20: R198.1@1231.5,3600 1231.5,3458.5 1315,3375 1735,3375 1860,3250 1896.83,3250 1906.57,3259.74 J24.3@1906.57,3337.64
PD2_IN_+: J25.3 R199.1 | length 1106.6
  Top Layer w20: v1(1200,2965) 1226.5,2938.5 R199.1@1226.5,2890
  Bottom Layer w20: v1(1200,2965) 1251.94,3016.94 1251.94,3146.94 1290,3185 1577,3185 1684,3292 1848,3292 1906.01,3233.99 J25.3@1906.01,3155
PD3_IN_+: J43.3 R202.1 | length 1158.5
  Top Layer w20: J43.3@5545,3154.99 5545,3090 5692,2943 v1(5692,2769) ; v1(6065,2550) R202.1@6118.5,2550
  Bottom Layer w20: v1(5692,2769) 6086,2769 6130,2725 6130,2615 v1(6065,2550)
PD4_IN_+: J44.3 R203.1 | length 953.4
  Top Layer w20: v1(6280,3115) R203.1@6280,3163.5
  Bottom Layer w20: J44.3@5545,3337.62 5545,3257 5595,3207 5595,3155 5635,3115 v1(6280,3115)
PD_OUT1: C4.1 J8.3 R8.2 | length 933.2
  Top Layer w10: R8.2@1663.7,3067.01 v1(1713.84,3067.01)
  Bottom Layer w10: C4.1@1663.7,3067.01 v1(1713.84,3067.01) 1922.01,3067.01 1955,3100 1955,3230 1985,3260 2135,3260 2165,3290 2165,3410 2185,3430 J8.3@2250,3430
PD_OUT1_ZC: R26.1 R204.1 | length 1712.9
  Top Layer w10: R26.1@1293.5,3896.85 1226.85,3896.85 1210,3880 1210,3695 1285,3620 1285,3460 1345,3400 1935,3400 1947,3388 1947,3107 1907.01,3067.01 R204.1@1765,3067.01
PD_OUT2: C5.1 J9.3 R10.2 | length 784.9
  Top Layer w20: R10.2@1631.12,2742.01 v1(1631.12,2693.51) 1758.51,2693.51 1865,2800 2120,2800 2180,2860 J9.3@2250,2860
  Bottom Layer w20: v1(1631.12,2693.51) C5.1@1631.12,2742.01
PD_OUT2_ZC: R32.1 R205.1 | length 1486.8
  Top Layer w10: R32.1@1345,3490.36 1345,3440 1365,3420 1945,3420 1967,3398 1967,2957 1752.01,2742.01 R205.1@1700,2742.01
PD_OUT3: C104.1 J45.3 R145.2 | length 915.7
  Top Layer w10: R145.2@5852.26,2903.54 5903.54,2903.54 v1(5905,2905)
  Bottom Layer w10: J45.3@5220,2860 5307,2860 5375,2792 5631,2792 5789,2950 5880,2950 5905,2925 v1(5905,2905) 5903.54,2903.54 C104.1@5852.26,2903.54
PD_OUT3_ZC: R163.1 R200.1 | length 1146.7
  Top Layer w10: R200.1@5780,2903.54 5780,3155.21 5779.96,3155.24 5779.96,3175.85 5780,3175.89 5780,3295 5825,3340 6225,3340 6325,3440 6325,3540 6318.32,3546.68 R163.1@6277.62,3546.68
PD_OUT4: C105.1 J46.3 R147.2 | length 861.2
  Top Layer w10: v1(5805,3228.54) R147.2@5849.84,3228.54
  Bottom Layer w10: J46.3@5215,3430 5349,3430 5374,3405 5575,3405 5595,3385 5595,3265 5665,3195 5771.46,3195 v1(5805,3228.54) C105.1@5849.84,3228.54
PD_OUT4_ZC: R169.1 R201.1 | length 1010.8
  Top Layer w10: R201.1@5981.5,3300 6007,3300 6022,3315 6250,3315 v1(6270,3335) ; R169.1@6226.12,3953.18 6278.18,3953.18 v1(6280,3955)
  Bottom Layer w10: v1(6270,3335) 6315,3380 6315,3525 6280,3560 v1(6280,3955)
VBIAS: J13.2 R14.1 R17.1 R47.1 R101.1 U3.5 U13.5 | length 6570.6
  Top Layer w15: U13.5@2160,1578.73 v1(2215.1,1578.73)
  Top Layer w20: U3.5@1085.47,1314.33 1049.33,1314.33 1035,1300 1035,1025 1116.6,943.4 R47.1@1273.26,943.4 1273.26,911.14 1306.68,877.73 v1(1546.08,877.73) R101.1@1606.08,877.73 ; v1(1240,2630) 1755,2630 1890,2765 2293,2765 v1(2365,2693) ; R17.1@1326.65,2960 R17.1@1330,2963.35 v1(1286.65,2963.35) 1250,3000 1250,3143.35 R14.1@1333.5,3226.85
  Bottom Layer w20: v1(1240,2630) 1240,2916.7 v1(1286.65,2963.35) ; v1(1546.08,877.73) 1660,991.65 1660,1154.4 2084.33,1578.73 v1(2215.1,1578.73) 2365,1728.63 v1(2365,2693) 2438,2693 3015,3270 3335,3270 3355,3290 J13.2@3355,3430
VBIASB: J47.2 R120.1 R136.1 R151.1 R154.1 U6.5 U15.5 | length 6072.7
  Top Layer w15: U6.5@5250.31,1749.69 5299.69,1749.69 ; v1(6327.8,1442.8) U15.5@6382.72,1442.8
  Top Layer w20: v1(4928,2763) 5622,2763 5665,2720 5665,2625 5690,2600 ; 5299.69,1749.69 5300,1750 5355,1695 v1(5577.5,1695) 5577.5,1835 5515,1897.5 5515,2115 5550,2150 5620,2150 5665,2195 5665,2575 5690,2600 ; R120.1@5631.67,1257.34 5631.67,1219.33 5646,1205 v1(5865,1205) R136.1@5865,1258.5 ; R154.1@6185,3008.5 v1(6235.8,3008.5) ; v1(6233.25,2673.7) R151.1@6182.45,2673.7 6182.45,2637.45 6145,2600 5690,2600
  Bottom Layer w20: J47.2@4035,3435 4035,3360 4065,3330 4361,3330 v1(4928,2763) ; v1(5577.5,1695) 5577.5,1622.5 5838.86,1361.14 5838.86,1231.14 v1(5865,1205) 6102.8,1442.8 v1(6327.8,1442.8) ; v1(6233.25,2673.7) 6184.96,2721.99 6184.96,2957.66 v1(6235.8,3008.5)
pads on no net: FID1.1 FID2.1 FID3.1 FID4.1 FID5.1 FID6.1 H1.1 H2.1 H3.1 H4.1 H9.1 H11.1 H13.1 H14.0 H15.1 H16.0 J1.2 J2.2 J31.2 J34.2 J48.2 J49.2 T1.3 T1.4 T2.3 T2.4 T3.3 T3.4 T4.3 T4.4 U5.12 U5.20 U10.1 U10.3 U10.7 U10.8 U11.2 U11.3 U11.6 U12.7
